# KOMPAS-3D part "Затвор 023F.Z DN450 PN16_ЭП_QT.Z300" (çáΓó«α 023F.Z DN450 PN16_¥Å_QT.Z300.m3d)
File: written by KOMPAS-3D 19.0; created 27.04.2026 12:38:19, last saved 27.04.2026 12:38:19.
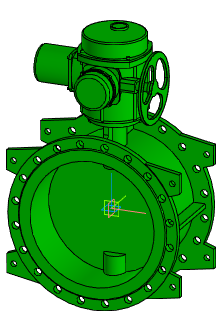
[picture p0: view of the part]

Document properties: Полное имя файла: Затвор 023F.Z DN450 PN16 +  электропривод QT.Z300.a3d

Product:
- Part/product: Затвор 023F.Z DN450 PN16_ЭП_QT.Z300
    Масса: 298.814
  - Body: Тело 1
      Масса: 299.329

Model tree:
1. Операция без истории:1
